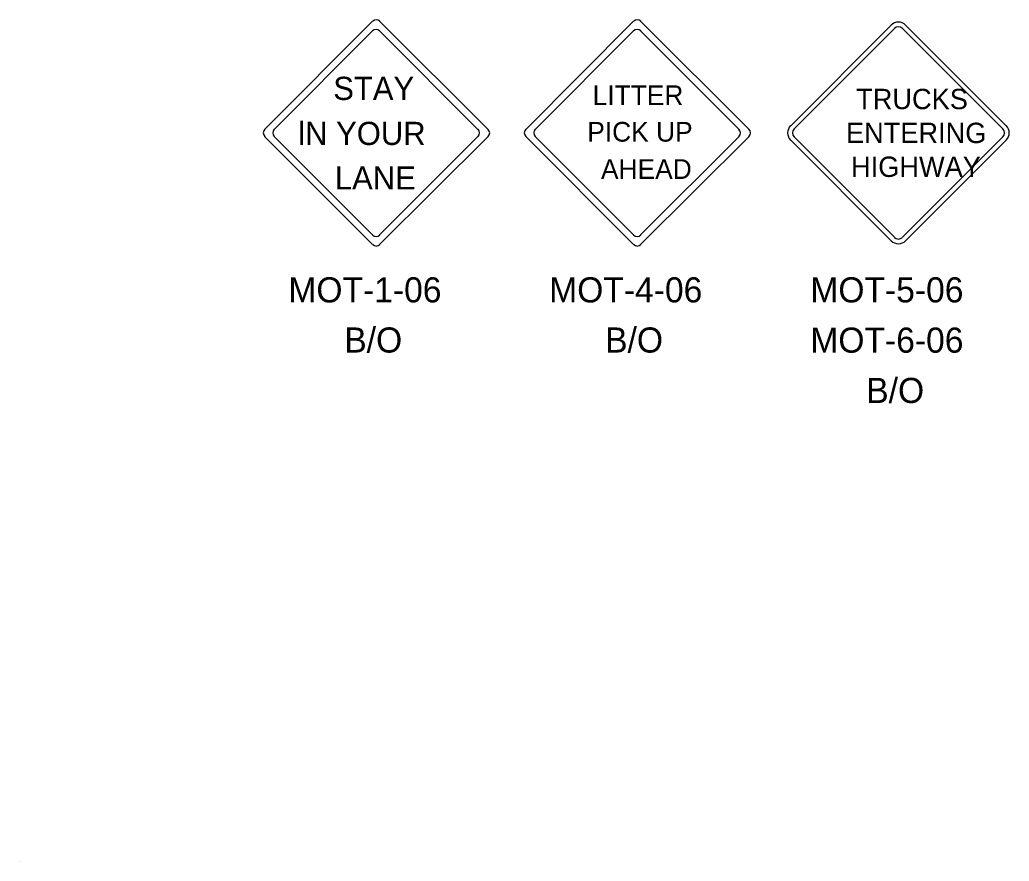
# Model space of a CAD drawing. Extents: x 10000 to 10794, y 10000 to 10499.
# Drawn here: x 10000 to 10137.8, y 10000 to 10117.1 of the extents above; entities that cross this region are included whole.
import ezdxf

# ---------------------------------------------------------------- set-up
doc = ezdxf.new("R2010")
doc.units = 0
for name, color, linetype in [('Default', 7, 'Continuous'), ('DSSheetNo', 7, 'Continuous'), ('DSText', 7, 'Continuous'), ('DSTitle', 7, 'Continuous'), ('Patterning', 7, 'Continuous'), ('PlotBorder_dp', 7, 'Continuous')]:
    doc.layers.add(name, color=color, linetype=linetype)

msp = doc.modelspace()

# ---------------------------------------------------------------- linework, layer by layer
at = {"layer": 'Default'}
msp.add_line((10000, 10000), (10000, 10000), dxfattribs=at)
at = {"layer": 'DSSheetNo'}
for p, q in [((10049.13, 10116.94), (10034.1, 10101.87)), ((10065.24, 10101.87), (10050.12, 10116.94)), ((10085.48, 10116.94), (10070.46, 10101.87)), ((10101.59, 10101.87), (10086.47, 10116.94)), ((10034.1, 10100.87), (10049.13, 10085.85)), ((10050.12, 10085.85), (10065.23, 10100.86)), ((10070.46, 10100.87), (10085.48, 10085.85)), ((10086.47, 10085.85), (10101.59, 10100.87))]:
    msp.add_line(p, q, dxfattribs=at)
for centre, start, end in [((10049.66, 10116.41), 45, 135), ((10086.02, 10116.41), 45, 135), ((10034.63, 10101.38), 135, 225), ((10064.74, 10101.37), 315, 45), ((10070.98, 10101.38), 135, 225), ((10101.05, 10101.38), 315, 45), ((10049.66, 10086.34), 225, 315), ((10086.02, 10086.34), 225, 315)]:
    msp.add_arc(centre, 0.709, start, end, dxfattribs=at)
at = {"layer": 'DSText'}
for p, q in [((10107.37, 10102.38), (10121.38, 10116.39)), ((10137.4, 10102.38), (10123.38, 10116.39)), ((10121.38, 10086.36), (10107.37, 10100.37)), ((10123.38, 10086.36), (10137.4, 10100.37))]:
    msp.add_line(p, q, dxfattribs=at)
for centre, start, end in [((10122.38, 10115.39), 45, 135), ((10108.37, 10101.38), 135, 225), ((10136.39, 10101.38), 315, 45), ((10122.38, 10087.37), 225, 315)]:
    msp.add_arc(centre, 1.42, start, end, dxfattribs=at)
at = {"layer": 'DSTitle'}
for p, q in [((10049.13, 10115.57), (10035.43, 10101.87)), ((10063.82, 10101.87), (10050.12, 10115.57)), ((10085.48, 10115.57), (10071.78, 10101.87)), ((10100.18, 10101.87), (10086.47, 10115.57)), ((10107.85, 10101.94), (10121.82, 10115.91)), ((10122.94, 10115.91), (10136.92, 10101.94)), ((10035.43, 10100.87), (10049.13, 10087.17)), ((10050.12, 10087.17), (10063.82, 10100.87)), ((10071.78, 10100.87), (10085.48, 10087.17)), ((10086.47, 10087.17), (10100.18, 10100.87)), ((10121.82, 10086.84), (10107.85, 10100.82)), ((10136.92, 10100.82), (10122.94, 10086.84))]:
    msp.add_line(p, q, dxfattribs=at)
for centre, radius, start, end in [((10049.62, 10115.06), 0.709, 45, 135), ((10085.98, 10115.06), 0.709, 45, 135), ((10122.38, 10115.35), 0.793, 45, 135), ((10035.94, 10101.38), 0.709, 135, 225), ((10063.32, 10101.38), 0.709, 315, 45), ((10072.29, 10101.38), 0.709, 135, 225), ((10099.67, 10101.37), 0.709, 315, 45), ((10108.41, 10101.38), 0.793, 135, 225), ((10136.36, 10101.38), 0.793, 315, 45), ((10049.63, 10087.67), 0.709, 225, 315), ((10085.98, 10087.67), 0.709, 225, 315), ((10122.38, 10087.4), 0.793, 225, 315)]:
    msp.add_arc(centre, radius, start, end, dxfattribs=at)
at = {"layer": 'Patterning'}
msp.add_line((10000, 10000), (10000, 10000), dxfattribs=at)

# ---------------------------------------------------------------- texts
at = {"layer": 'PlotBorder_dp'}
for s, height, p in [('STAY ', 3.227, (10043.66, 10105.96)), ('LITTER', 2.743, (10079.79, 10105.25)), ('TRUCKS', 2.831, (10116.49, 10104.68)), ('lN YOUR', 3.228, (10038.78, 10099.69)), ('PICK UP', 2.743, (10079.04, 10100.16)), ('ENTERING', 2.831, (10115.07, 10099.96)), ('AHEAD', 2.743, (10080.95, 10094.97)), ('HIGHWAY', 2.831, (10115.78, 10095.25)), ('LANE', 3.228, (10043.88, 10093.5)), ('MOT-1-06', 3.5, (10037.41, 10077.78)), ('MOT-4-06', 3.5, (10073.74, 10077.78)), ('MOT-5-06', 3.5, (10110.11, 10077.78)), ('B/O', 3.5, (10045.2, 10070.8)), ('B/O', 3.5, (10081.53, 10070.8)), ('MOT-6-06', 3.5, (10110.11, 10070.78)), ('B/O', 3.5, (10117.9, 10063.78))]:
    msp.add_text(s, height=height, dxfattribs=at).set_placement(p)

doc.saveas('drawing.dxf')
